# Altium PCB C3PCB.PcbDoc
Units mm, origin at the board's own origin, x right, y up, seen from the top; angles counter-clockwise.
Board outline 50 x 80 mm, 4 copper layers (Top Layer, Int1 (GND), Int2 (PWR), Bottom Layer), stack 1.527 mm thick; 54 components, 42 nets, 181 pads, 145 vias.
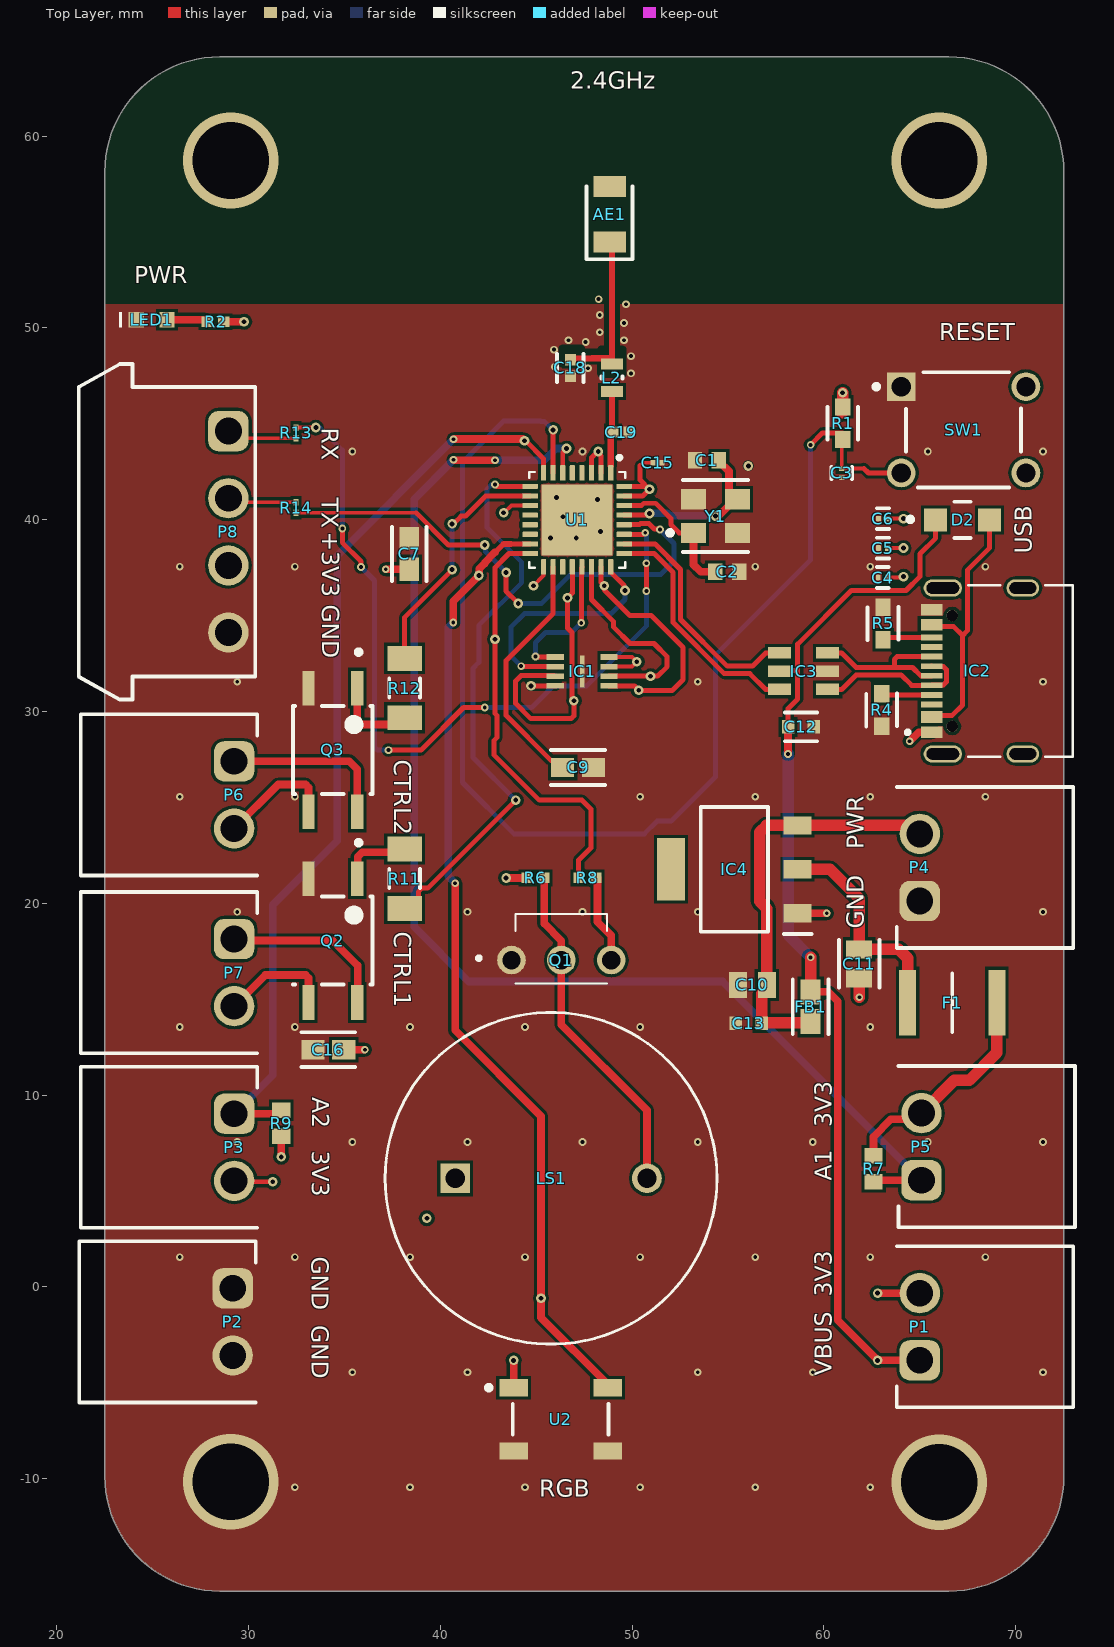
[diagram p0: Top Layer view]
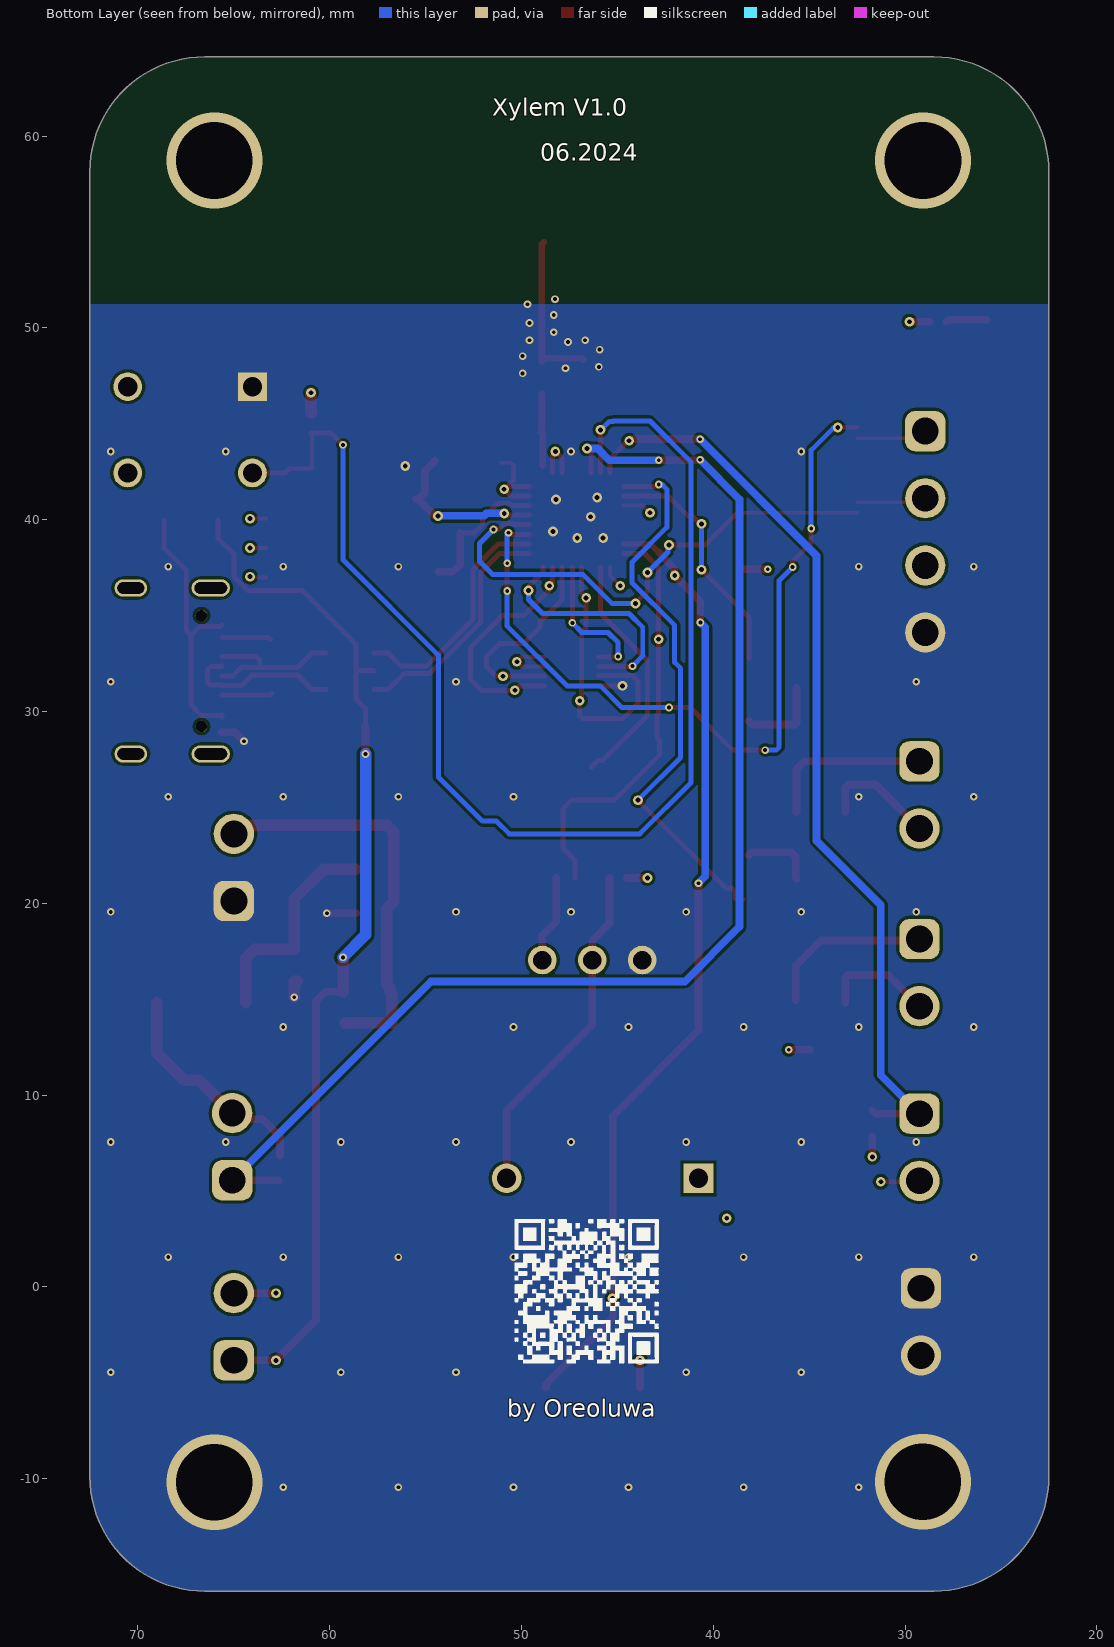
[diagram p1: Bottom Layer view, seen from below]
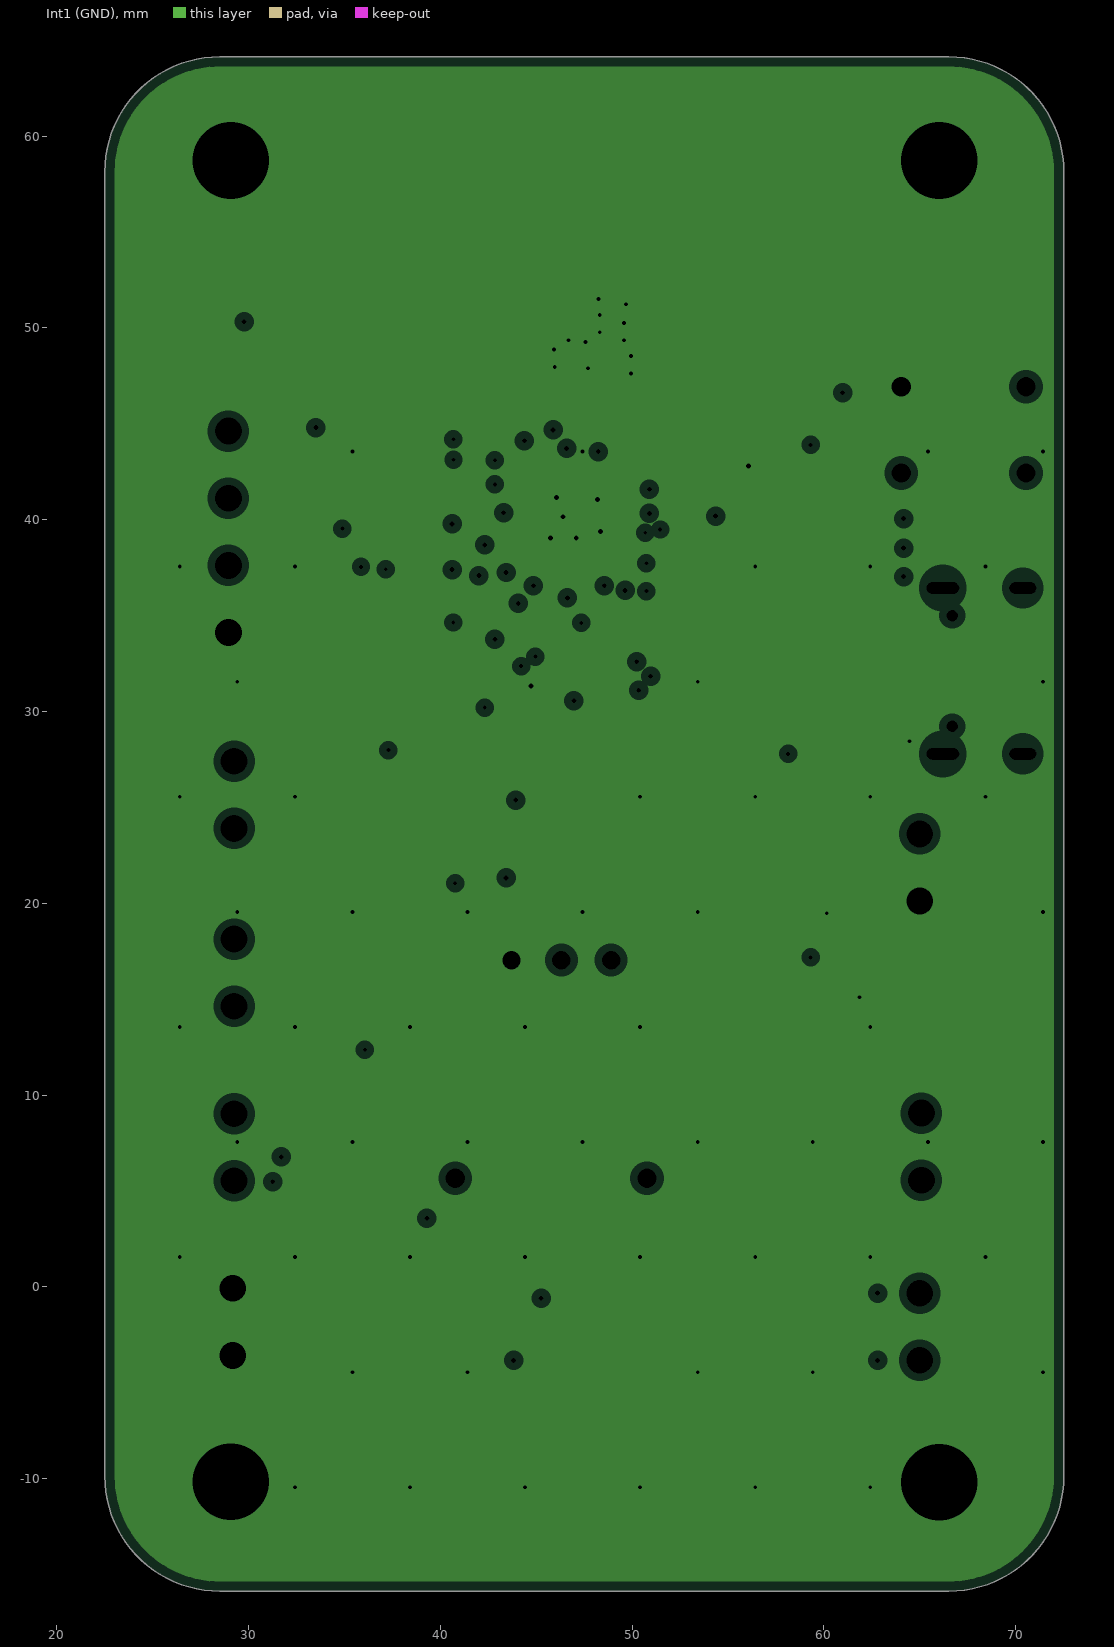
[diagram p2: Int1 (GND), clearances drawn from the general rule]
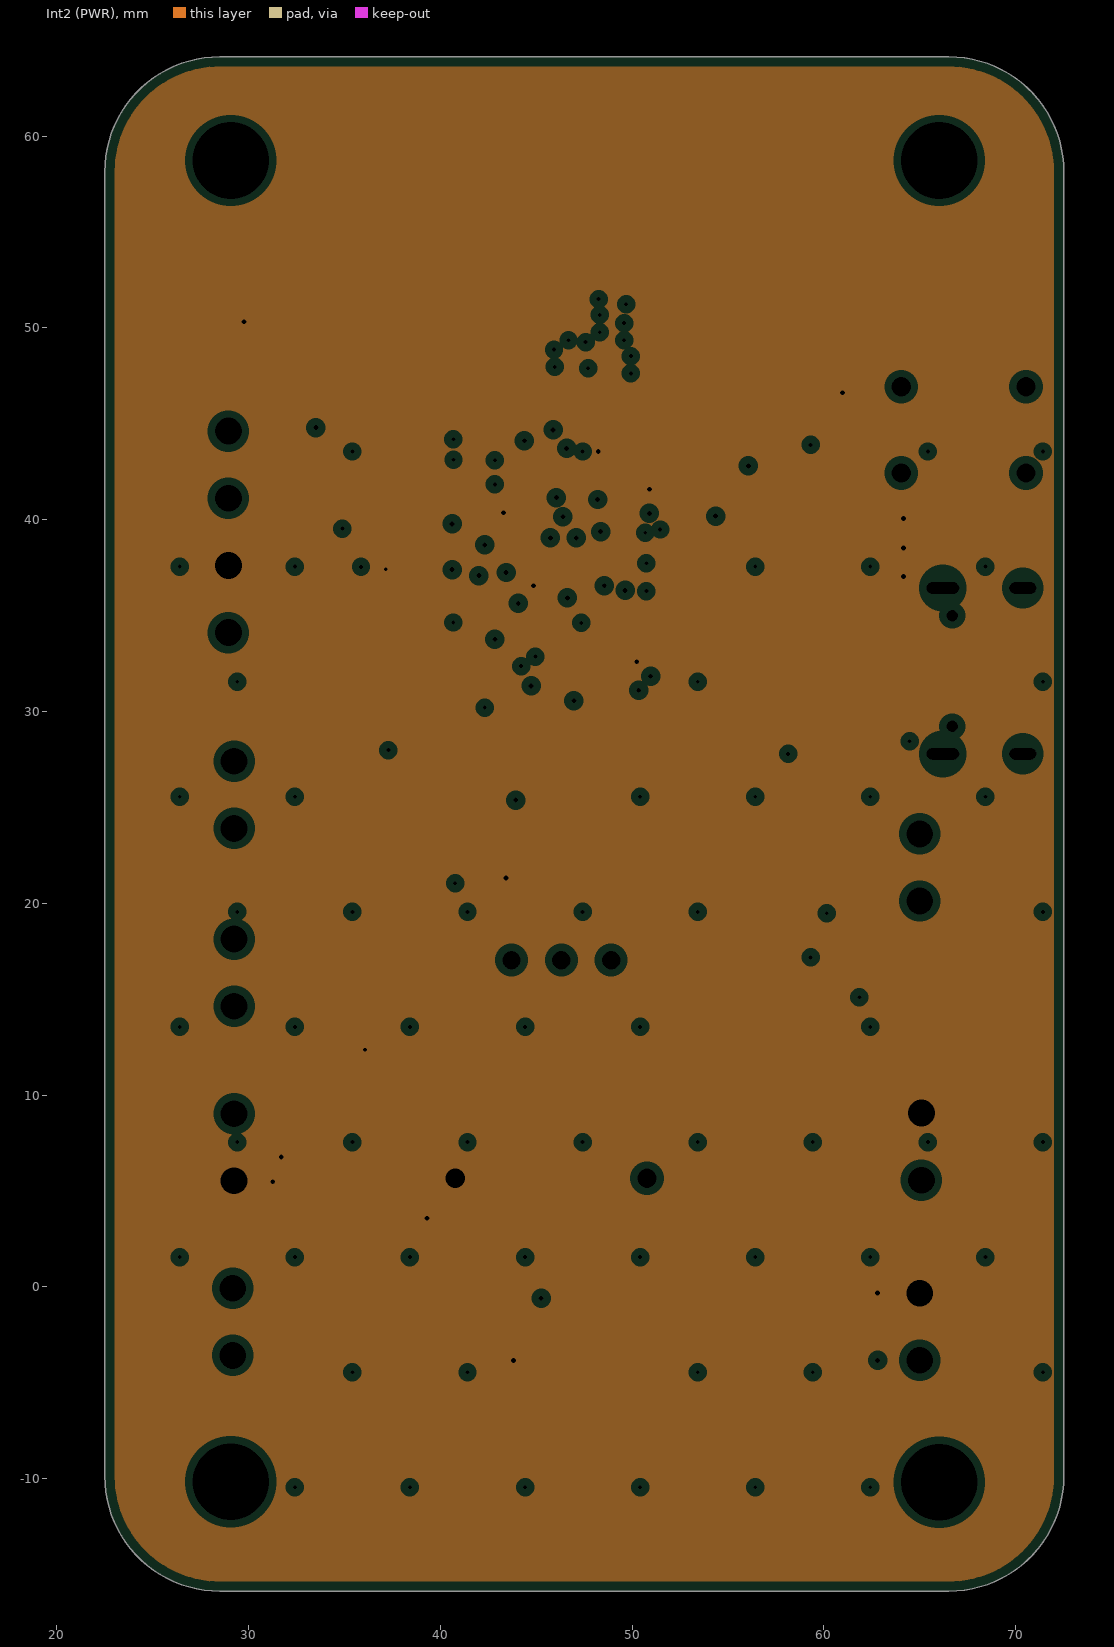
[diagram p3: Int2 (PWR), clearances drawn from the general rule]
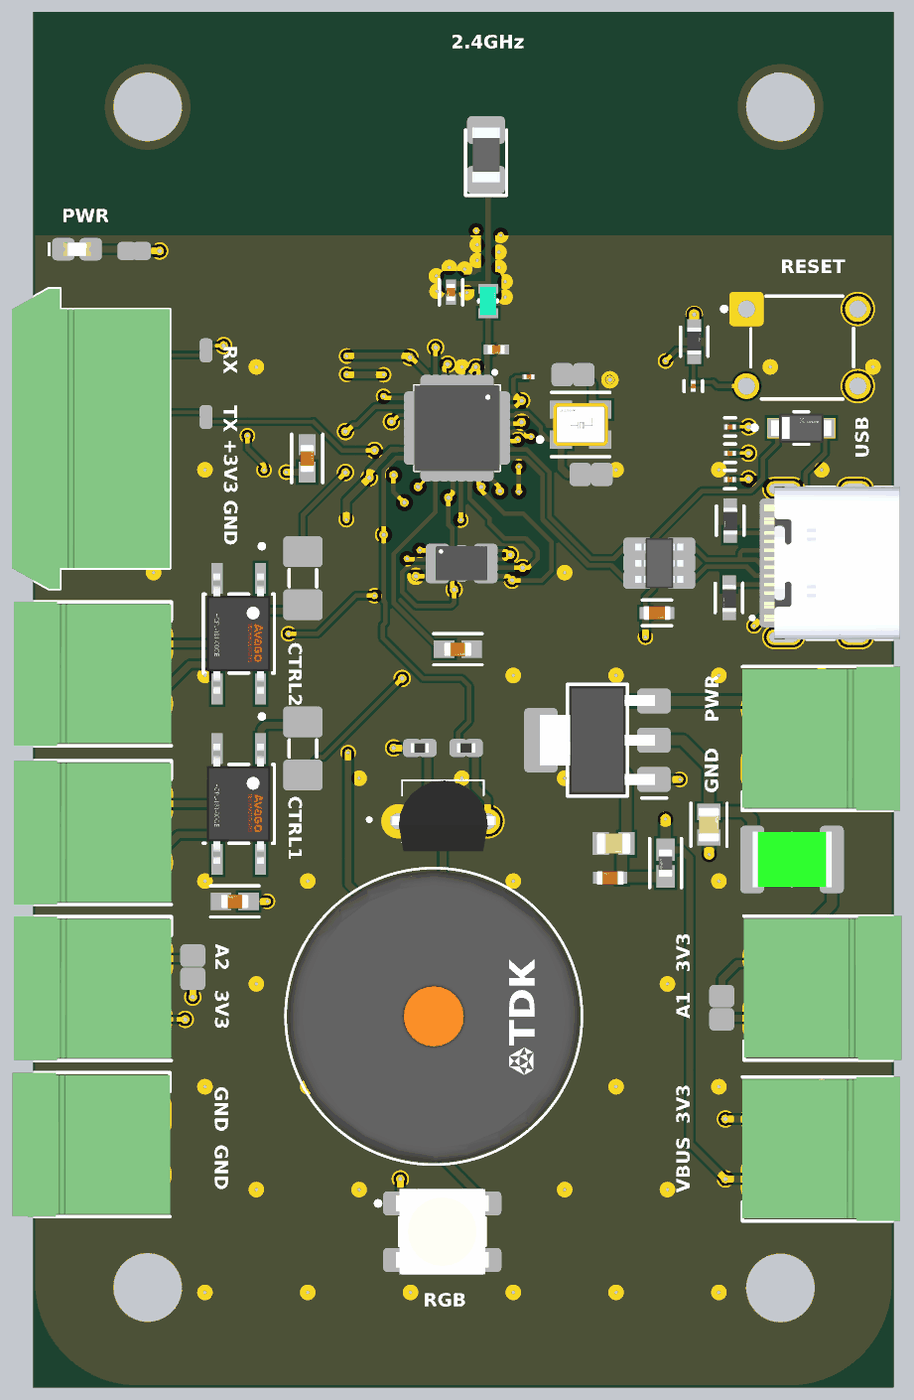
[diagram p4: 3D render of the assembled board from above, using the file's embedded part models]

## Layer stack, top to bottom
Top Solder: solder mask 0.0254, SM-001, Dk 4
Top Layer: signal copper 0.0175
Dielectric 1: prepreg 0.196, PP-017, Dk 4.56
Int1 (GND): plane copper 0.035, net GND
Dielectric 3: core 1.03, Core-039, Dk 4.6
Int2 (PWR): plane copper 0.035, net +3V3
Dielectric 5: prepreg 0.196, PP-017, Dk 4.56
Bottom Layer: signal copper 0.0175
Bottom Solder: solder mask 0.0254, SM-001, Dk 4

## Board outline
22.504,-9.865 22.504,58.135 cw(c28.504,58.135) 28.504,64.135 66.504,64.135 cw(c66.504,58.135) 72.504,58.135 72.504,-9.865 cw(c66.504,-9.865) 66.504,-15.865 28.504,-15.865 cw(c28.504,-9.865)

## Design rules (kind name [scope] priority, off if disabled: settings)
Clearance [All] p1: gap=0.15 ignorepadtopadclearanceinfootprint=TRUE except(0.01: Arc-SMDPad Track-SMDPad SMDPad-SMDPad; 0.1: Arc-Arc Arc-Track Track-Track)
DiffPairsRouting [InDifferentialPair('USBMCU_D')] p1: maxlimit=0.127 minlimit=0.127 mostfreqgap=0.127 toplayer_minwidth=0.26 toplayer_maxwidth=0.26 toplayer_prefwidth=0.26 bottomlayer_minwidth=0.26 bottomlayer_maxwidth=0.26 bottomlayer_prefwidth=0.26 impedanceprofiledriven=TRUE impedanceprofileid={74920327-C2D2-4B69-8C3B-EE058ED59872} impedanceprofilevalue=90.000000 maxuncoupledlength=12.7
DiffPairsRouting DiffPairsRouting_1 [InDifferentialPair('USBIN_D')] p2: maxlimit=0.127 minlimit=0.127 mostfreqgap=0.127 toplayer_minwidth=0.26 toplayer_maxwidth=0.26 toplayer_prefwidth=0.26 bottomlayer_minwidth=0.26 bottomlayer_maxwidth=0.26 bottomlayer_prefwidth=0.26 impedanceprofiledriven=TRUE impedanceprofileid={74920327-C2D2-4B69-8C3B-EE058ED59872} impedanceprofilevalue=90.000000 maxuncoupledlength=12.7
HoleSize [All] p1: absolutevalues=TRUE maxlimit=7.62 minlimit=0.2 maxpercent=80.000 minpercent=20.000
MinimumAnnularRing [All] p1: minimumring=0
MinimumSolderMaskSliver [All] p1: minsoldermaskwidth=0
PasteMaskExpansion [All] p1: expansion=0.254
PlaneClearance [All] p1: clearance=0.381
PlaneConnect [All] p1: pad.planeconnectstyle=Relief pad.reliefexpansion=0.508 pad.reliefentries=4 pad.reliefconductorwidth=0.254 pad.reliefairgap=0.254 via.planeconnectstyle=Direct via.reliefexpansion=0.508 via.reliefentries=4 via.reliefconductorwidth=0.254 via.reliefairgap=0.254
PolygonConnect [All] p1: connectstyle=Direct reliefconductorwidth=0.254 reliefentries=4 polygonreliefangle="90 Angle" airgapwidth=0.254
RoutingVias [All] p1: holewidth=0.3 width=0.508 viastyle="Through Hole" minholewidth=0.19 minwidth=0.3 maxholewidth=15 maxwidth=15
SMDNeckDown [All] p1: percent=150.000
SilkToSilkClearance [All] p1: silktosilkclearance=0.1
SilkToSolderMaskClearance SilkscreenOverComponentPads [IsPad] p1: minsilkscreentomaskgap=0.1 clearancetoexposedcopper=TRUE
SolderMaskExpansion [All] p1: expansion=0.254 istentingtop=FALSE
UnRoutedNet [All] p1: checkbadconnections=TRUE
Width [InNet('ANT_RF')] p1: maxlimit=0.331 minlimit=0.331 preferedwidth=0.331 impedanceprofiledriven=TRUE impedanceprofileid={D2943A05-8640-44C0-B199-8AFC77BF5E13} impedanceprofilevalue=50.000000 minimp=50.000000 maximp=50.000000 favimp=50.000000
21 further rules are at their usual default settings.

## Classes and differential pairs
differential pair class DIF_USB: USBIN_D USBMCU_D
differential pair USBMCU_D: +USBMCU_D_P -USBMCU_D_N
differential pair USBIN_D: +USBIN_D_P -USBIN_D_N

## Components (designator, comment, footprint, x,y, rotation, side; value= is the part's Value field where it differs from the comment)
AE1 "W3008" ANTC3216X115N 48.825,55.925 r90 top
C1 "10pF" CAPC1608X90X35LL10T15 53.898,43.099 r0 top
C2 "10pF" CAPC1608X90X35LL10T15 54.957,37.282 r180 top
C3 "100nF" FP-GRM033-0_03-MFG 60.925,42.435 r270 top
C4 "100nF" FP-GRM033-0_03-MFG 63.064,36.986 r180 top
C5 "100nF" FP-GRM033-0_03-MFG 63.075,38.52 r180 top
C6 "100nF" FP-GRM033-0_03-MFG 63.075,40.054 r180 top
C7 "10u" FP-GRM188-0_1-e0_2_0_55-IPC_A 38.379,38.218 r90 top
C9 "10u" FP-GRM188-0_1-e0_2_0_55-IPC_A 47.177,27.082 r0 top
C10 "22uf/0805" FP-C0805C226M9PACTU-MFG 56.272,15.746 r180 top
C11 "22uf/0805" FP-C0805C226M9PACTU-MFG 61.836,16.846 r270 top
C12 "2u2/0603/15%" FP-GRM188-0_1-e0_2_0_5-MFG 58.801,29.197 r0 top
C13 "2u2/0603/15%" FP-GRM188-0_1-e0_2_0_5-MFG 56.075,13.741 r180 top
C15 "100nF" FP-GRM033-0_03-MFG 51.322,42.97 r0 top
C16 "10u" FP-GRM188-0_1-e0_2_0_55-IPC_A 34.158,12.368 r180 top
C18 "3.3pf/0402" FP-GJM155-0_05-IPC_B 46.775,47.909 r270 top
C19 "3.3pf/0402" FP-GJM155-0_05-IPC_B 49.42,44.57 r0 top
D2 "60A/2A" FP-SOD123W-MFG 67.225,39.988 r0 top
F1 "16V Resetable Fuse" FUSC4632X160N 66.686,14.817 r0 top
FB1 "120R" FP-BLM18-0_15-t0_8-IPC_A 59.301,14.605 r270 top
IC1 "W25Q16JVUXIQ" SON50P300X200X60-9N 47.394,32.089 r0 top
IC2 "TYPE-C-31-M-12" HRO_TYPE-C-31-M-12 70.366,32.114 r90 top
IC3 "USBLC6-2SC6" SOT95P280X145-6N 58.939,32.101 r180 top
IC4 "AMS1117-3.3" SOT229P700X180-4N 55.325,21.772 r180 top
L2 "2.2nH" FP-LQW18AN_80-MFG 48.944,47.403 r90 top
LED1 "GREEN" WL-SMCW_0603_150060xx75000 24.947,50.423 r0 top
LS1 "PS1720P02" FP-PS1720P02-MFG 45.771,5.663 r0 top
P1 "691322110002" 691322110002 68.395,-2.076 r90 top
P2 "691322110002" 691322110002 25.773,-1.822 r270 top
P3 "691322110002" 691322110002 25.85,7.282 r270 top
P4 "691322110002" 691322110002 68.395,21.871 r90 top
P5 "691322110002" 691322110002 68.479,7.311 r90 top
P6 "691322110002" 691322110002 25.85,25.653 r270 top
P7 "691322110002" 691322110002 25.85,16.387 r270 top
P8 "691305140004" 691305140004 25.747,39.368 r270 top
Q1 "KSC1815YTA" BC33740TA 45.408,17.627 r0 top
Q2 "HCPL-181-00CE" FP-SO-4-MFG 34.392,18.059 r270 top
Q3 "HCPL-181-00CE" FP-SO-4-MFG 34.392,27.994 r270 top
R1 "5k1/0603" FP-RT0603-MFG 60.974,45.027 r90 top value=5.1KΩ
R2 "220R/50V/5%" RESC1005X40X25NL05T10 28.281,50.32 r180 top
R4 "5k1/0603" FP-RT0603-MFG 63.011,30.082 r270 top value=5.1KΩ
R5 "5k1/0603" FP-RT0603-MFG 63.079,34.592 r270 top value=5.1KΩ
R6 "1k" RESC1005X40X25NL05T05 44.958,21.322 r180 top
R7 "165R/75V/1%" RESC1608X55X30NL15T15 62.586,6.163 r90 top
R8 "1k/1%/0402" RESC1005X40X25NL05T05 47.663,21.322 r180 top
R9 "165R/75V/1%" RESC1608X55X30NL15T15 31.704,8.532 r270 top
R11 "220R/1216" RESC3216X60X45ML10T20 38.135,21.289 r90 top
R12 "220R/1216" RESC3216X60X45ML10T20 38.135,31.224 r270 top
R13 "470R/25V/1%" RESC0603X26X15LL03T05 32.48,44.524 r270 top
R14 "470R/25V/1%" RESC0603X26X15LL03T05 32.48,40.635 r90 top
SW1 "B3F-1000" OMRON-B3F-1000-4_V 67.277,44.685 r0 top
U1 "ESP32C3" QFN32_5X5MM 47.13,39.988 r270 top
U2 "1655" ADA-RGB-1655_V 46.271,-6.902 r0 top
Y1 "40.000MHZ" FP-ABM8-MFG 54.346,40.19 r0 top

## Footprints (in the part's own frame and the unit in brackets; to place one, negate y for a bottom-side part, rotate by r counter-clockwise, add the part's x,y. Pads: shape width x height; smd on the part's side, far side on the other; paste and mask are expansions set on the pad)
691305140004 [mm] "Horizontal PCB Header with Plastic Latch, pitch 3.5mm, 04p"
  rrect50% 2.1x2.1 hole 1.4: 1(-5.25,3.2)
  round 2.1 hole 1.4: 2(-1.75,3.2) 3(1.75,3.2) 4(5.25,3.2)
  silkscreen extent -8.75,-4.6 8.75,4.6, body extent -8.75,-4.6 8.75,4.6, height 7.25
691322110002 [mm] "Horizontal PCB Header, pitch 3.5mm, 02p"
  rrect50% 2.1x2.1 hole 1.4: 1(-1.75,3.4)
  round 2.1 hole 1.4: 2(1.75,3.4)
  silkscreen extent -4.2,-4.6 4.2,4.6, body extent -4.2,-4.6 4.2,4.6, height 7.3
ADA-RGB-1655_V [mm] "SMD, 4-Leads, Body 5x5mm"
  rect 1.5x0.9 smd: 1(-2.45,1.65) 2(-2.45,-1.65) 3(2.45,-1.65) 4(2.45,1.65)
  silkscreen extent -3.87,-0.8 2.5,1.77, body extent -2.7,-2.5 2.7,2.5, height 1.68
ANTC3216X115N [mm]
  rect 1.1x1.7 smd: 1(-1.45,0) 2(1.45,0)
  silkscreen extent -2.35,-1.2 1.45,1.2, body extent -1.6,-0.8 1.6,0.8, height 1.15
BC33740TA [mm]
  round 1.493 hole 0.96: 1(-1.7,-0.585) 2(0.9,-0.585) 3(3.5,-0.585)
  silkscreen extent -3.5,-1.81 3.28,1.81, body extent -2.16,-2.34 4,1.79, height 8.67
CAPC1608X90X35LL10T15 [mm] "Chip Capacitor, 2-Leads, Body 1.60x0.80mm, IPC High Density"
  rect 0.75x0.85 smd: 1(-0.625,0) 2(0.625,0)
  body extent -0.85,-0.45 0.85,0.45, height 0.9
FP-ABM8-MFG [mm]
  rect 1.3x1.05 smd paste+0 mask+0: 1(-1.15,-0.875) 2(1.15,-0.875) 3(1.15,0.875) 4(-1.15,0.875)
  silkscreen extent -2.5,-1.88 1.7,1.88, body extent -1.9,-1.5 1.9,1.5, height 0.25
FP-BLM18-0_15-t0_8-IPC_A [mm]
  rect 1.306x1.058 smd paste+0 mask+0: 1(-0.776,0) 2(0.776,0)
  silkscreen extent -1.43,-0.93 1.43,0.93, body extent -1.93,-1.03 1.93,1.03, height 0.25
FP-C0805C226M9PACTU-MFG [mm]
  rect 0.95x1.35 smd paste+0 mask+0: 1(-0.75,0) 2(0.75,0)
  body extent -1.4,-0.85 1.4,0.85, height 0.25
FP-GJM155-0_05-IPC_B [mm]
  rect 0.615x0.572 smd paste+0 mask+0: 1(-0.429,0) 2(0.429,0)
  silkscreen extent -0.74,-0.69 0.74,0.69, body extent -0.89,-0.44 0.89,0.44, height 0.25
FP-GRM033-0_03-MFG [mm]
  rect 0.25x0.3 smd paste+0 mask+0: 1(-0.238,0) 2(0.238,0)
  silkscreen extent -0.32,-0.54 0.32,0.54, body extent -0.46,-0.27 0.46,0.27, height 0.25
FP-GRM188-0_1-e0_2_0_5-MFG [mm]
  rect 0.65x0.7 smd paste+0 mask+0: 1(-0.675,0) 2(0.675,0)
  silkscreen extent -0.85,-0.75 0.85,0.75, body extent -1.1,-0.55 1.1,0.55, height 0.25
FP-GRM188-0_1-e0_2_0_55-IPC_A [mm]
  rect 1.208x1.012 smd paste+0 mask+0: 1(-0.802,0) 2(0.802,0)
  silkscreen extent -1.41,-0.91 1.41,0.91, body extent -1.91,-1.01 1.91,1.01, height 0.25
FP-LQW18AN_80-MFG [mm]
  rect 0.57x1.15 smd paste+0 mask+0: 1(-0.715,0) 2(0.715,0)
  silkscreen extent -0.06,-0.55 0.06,0.55, body extent -1.1,-0.67 1.1,0.67, height 0.25
FP-PS1720P02-MFG [mm]
  rect 1.55x1.55 hole 1 paste-2539.97 mask+0: 1(-5,0)
  round 1.55 hole 1 paste-2539.97 mask+0: 2(5,0)
  silkscreen extent -8.65,-8.65 8.65,8.65, body extent -8.75,-8.75 8.75,8.75, height 0.25
FP-RT0603-MFG [mm]
  rect 0.9x0.8 smd paste+0 mask+0: 1(-0.85,0) 2(0.85,0)
  silkscreen extent -0.85,-0.81 0.86,0.8, body extent -1.4,-0.55 1.4,0.55, height 0.25
FP-SO-4-MFG [mm]
  rect 1.8x0.64 smd paste+0 mask+0: 1(-3.23,1.27) 2(-3.23,-1.27) 3(3.23,-1.27) 4(3.23,1.27)
  silkscreen extent -5.23,-2.07 2.3,2.07, body extent -4.23,-2.17 4.23,2.17, height 0.25
FP-SOD123W-MFG [mm]
  rect 1.2x1.2 smd paste-1000 mask+0: 1(-1.4,0) 2(1.4,0)
  silkscreen extent -2.85,-0.95 0.43,0.95, body extent -2.2,-1.05 2.2,1.05, height 0.25
FUSC4632X160N [mm]
  rect 0.89x3.43 smd: 1(-2.325,0) 2(2.325,0)
  silkscreen extent 0,-1.52 0,1.52, body extent -2.3,-1.62 2.3,1.62, height 1.6
HRO_TYPE-C-31-M-12 [mm]
  rect 0.6x1.14 smd mask+0.05: A1_B12(-3.2,4.75) A4_B9(-2.4,4.75) B1_A12(3.2,4.75) B4_A9(2.4,4.75)
  rect 0.3x1.14 smd mask+0.05: A5(-1.25,4.75) A6(-0.25,4.75) A7(0.25,4.75) A8(1.25,4.75) B5(1.75,4.75) B6(0.75,4.75) B7(-0.75,4.75) B8(-1.75,4.75)
  oval 0.9x2 hole 0.6 slot 1.7 at 90 deg: S1(-4.325,4.17) S2(4.325,4.17)
  oval 0.9x1.7 hole 0.6 slot 1.4 at 90 deg: S3(-4.325,0) S4(4.325,0)
  round 0.6 hole 0.6 unplated: ""(-2.89,3.68) ""(2.89,3.68)
  silkscreen extent -4.47,-2.6 4.47,6.1, body extent -4.47,-2.6 4.47,5.31, height 3.31
OMRON-B3F-1000-4_V [mm] "TH, 4-Leads, Body 6x6mm"
  rect 1.5x1.5 hole 1 paste-2539.97: 1(-3.25,2.25)
  round 1.5 hole 1 paste-2539.97: 2(3.25,2.25) 4(3.25,-2.25)
  round 1.5 hole 1 paste-2539.97 mask+0.102: 3(-3.25,-2.25)
  silkscreen extent -4.67,-3 3,3, body extent -3,-3 3,3, height 4.5
QFN32_5X5MM [mm]
  rrect25% 0.81x0.27 smd: 1(-2.45,1.75) 2(-2.45,1.25) 3(-2.45,0.75) 4(-2.45,0.25) 5(-2.45,-0.25) 6(-2.45,-0.75) 7(-2.45,-1.25) 8(-2.45,-1.75) 17(2.45,-1.75) 18(2.45,-1.25) 19(2.45,-0.75) 20(2.45,-0.25) 21(2.45,0.25) 22(2.45,0.75) 23(2.45,1.25) 24(2.45,1.75)
  rrect25% 0.27x0.81 smd: 9(-1.75,-2.45) 10(-1.25,-2.45) 11(-0.75,-2.45) 12(-0.25,-2.45) 13(0.25,-2.45) 14(0.75,-2.45) 15(1.25,-2.45) 16(1.75,-2.45) 25(1.75,2.45) 26(1.25,2.45) 27(0.75,2.45) 28(0.25,2.45) 29(-0.25,2.45) 30(-0.75,2.45) 31(-1.25,2.45) 32(-1.75,2.45)
  rect 3.7x3.7 smd paste-1.4: 33(0,0)
  silkscreen extent -3.35,-2.5 2.5,2.5, body extent -2.5,-2.5 2.5,2.5, height 0.9
RESC0603X26X15LL03T05 [mm] "Chip Resistor, 2-Leads, Body 0.60x0.30mm, IPC High Density"
  rect 0.35x0.25 smd: 1(-0.275,0) 2(0.275,0)
  body extent -0.32,-0.16 0.31,0.17, height 0.26
RESC1005X40X25NL05T05 [mm] "Chip Resistor, 2-Leads, Body 1.05x0.55mm, IPC Medium Density"
  rect 0.55x0.55 smd: 1(-0.45,0) 2(0.45,0)
  body extent -0.53,-0.28 0.53,0.28, height 0.4
RESC1005X40X25NL05T10 [mm] "Chip Resistor, 2-Leads, Body 1.00x0.50mm, IPC Medium Density"
  rect 0.6x0.55 smd: 1(-0.425,0) 2(0.425,0)
  body extent -0.53,-0.27 0.53,0.28, height 0.4
RESC1608X55X30NL15T15 [mm] "Chip Resistor, 2-Leads, Body 1.60x0.80mm, IPC Medium Density"
  rect 0.8x0.95 smd: 1(-0.675,0) 2(0.675,0)
  body extent -0.87,-0.48 0.87,0.48, height 0.55
RESC3216X60X45ML10T20 [mm] "Chip Resistor, 2-Leads, Body 3.20x1.60mm, IPC Low Density"
  rect 1.3x1.8 smd: 1(-1.55,0) 2(1.55,0)
  silkscreen extent -0.5,-0.8 0.5,0.8, body extent -1.65,-0.85 1.65,0.85, height 0.6
SON50P300X200X60-9N [mm]
  rect 0.9x0.3 smd: 1(-1.4,0.75) 2(-1.4,0.25) 3(-1.4,-0.25) 4(-1.4,-0.75) 5(1.4,-0.75) 6(1.4,-0.25) 7(1.4,0.25) 8(1.4,0.75)
  rect 0.25x1.65 smd: 9(0,0)
  body extent -1.5,-1 1.5,1, height 0.6
SOT95P280X145-6N [mm]
  rect 1.2x0.6 smd: 1(-1.25,0.95) 2(-1.25,0) 3(-1.25,-0.95) 4(1.25,-0.95) 5(1.25,0) 6(1.25,0.95)
  body extent -1.4,-1.46 1.4,1.46, height 1.45
SOT229P700X180-4N [mm]
  rect 1.45x0.95 smd: 1(-3.3,2.29) 2(-3.3,0) 3(-3.3,-2.29)
  rect 1.45x3.25 smd: 4(3.3,0)
  silkscreen extent -4.04,-3.25 1.75,3.37, body extent -3.35,-3.15 3.35,3.15, height 1.8
WL-SMCW_0603_150060xx75000 [mm] "SMD Mono-color Chip LED, body 1.6x0.8mm"
  rect 0.8x0.8 smd: 1(-0.8,0) 2(0.8,0)
  silkscreen extent -1.71,-0.4 -1.56,0.4, body extent -0.8,-0.4 0.8,0.4, height 0.7

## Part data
AE1: "Antenna", Manufacturer_Name=PULS
C1 C2: library part CMP-2006-02592-1, Manufacturer=Murata, Part Number=GRM1885C1H100JA01D
C3 C4 C5 C6 C15: library part CMP-06035-000062-2, "Chip Multilayer Ceramic Capacitors for General Purpose, 0201, 0.10uF, X5R, 15%, 10%, 6.3V", Case Code (Imperial)=0201, Case Code (Metric)=0603, Dielectric=X5R, Max Operating Temperature=85°C, Min Operating Temperature=-55°C, Package Quantity=1, Tolerance=10%, Voltage=6.3V
C7 C9 C16: library part CMP-2006-02792-2, "Chip Multilayer Ceramic Capacitors for General Purpose, 0603, 10uF, X5R, 15%, 20%, 6.3V", Capacitance=10uF, Case Code (Imperial)=0603, Case Code (Metric)=1608, Dielectric=X5R, Max Operating Temperature=85°C, Min Operating Temperature=-55°C, Package Quantity=4000, Tolerance=20%, Voltage=6.3V
C10 C11: library part CMP-2007-01021-2, "CAP CER 22UF 6.3V X5R 0805", Capacitance=22uF, Case Code (Imperial)=0805, Case Code (Metric)=2012, Dielectric=X5R, Dielectric Material=Ceramic, Max Operating Temperature=85°C, Min Operating Temperature=-55°C, Package Quantity=2500, Tolerance=20%, Voltage=6.3V
C12 C13: library part CMP-2006-02836-2, "Chip Multilayer Ceramic Capacitors for General Purpose, 0603, 2.2uF, X7R, 15%, 10%, 10V", Capacitance=2.2uF, Case Code (Imperial)=0603, Case Code (Metric)=1608, Dielectric=X7R, Max Operating Temperature=125°C, Min Operating Temperature=-55°C, Package Quantity=1, Tolerance=10%, Voltage=10V
C18 C19: library part CMP-2008-03847-2, "Multi-Layer Ceramic Capacitor 3.3pF C0G  ±0.25pF 0402 Paper T/R", Capacitance=3.3pF, Case Code (Imperial)=0402, Case Code (Metric)=1005, Dielectric=C0G, Max Operating Temperature=125°C, Min Operating Temperature=-55°C, Package Quantity=1, Voltage=50V
D2: library part CMP-14398-000040-1, "DIODE SCHOTTKY 60V 2A CFP3"
F1: library part MF-MSMF250_16X, "Fuse", Manufacturer_Name=Bourns, Manufacturer_Part_Number=MF-MSMF250/16X
FB1: library part CMP-0686-00557-7, "Chip Ferrite Bead, 0603, 120Ω @ 100MHz, 0.05Ω, 25%, 2A", Case Code (Imperial)=0603, Case Code (Metric)=1608, Current Rating=2A, DC Resistance (DCR)=50mR, Frequency=100MHz, Max Operating Temperature=125°C, Min Operating Temperature=-55°C, Package Quantity=1, Tolerance=25%
IC1: library part CMP-031-00015-1, "NOR Flash Serial (SPI, Dual SPI, Quad SPI) 3V/3.3V 16M-bit 2M x 8 6ns 8-Pin USON EP T/R", Case/Package="UFDFN-8 Winbond"
IC2: library part CMP-002-00071-1, "USB Connectors 24 Receptacle 1 8.94*7.3mm RoHS", Case/Package=Package
IC3: "Integrated Circuit", Manufacturer_Name=STMicroelectronics, Mouser Part Number=511-USBLC6-2SC6
IC4: "Integrated Circuit", Manufacturer_Name=Advanced
L2: library part CMP-06042-009804-1, "Wire Wound RF Inductor 2.2nH ±0.2nH 3200mA 0.018Ω 0603 (1608)", Case/Package=0603, Current Rating=3.2A, DC Resistance (DCR)=18mR, Max Operating Temperature=125°C, Min Operating Temperature=-55°C, Package Quantity=4000, Resistor Type=Wirewound, Self Resonant Frequency=15GHz, Test Frequency=100MHz
LED1: library part CMP-1426-00006-6, Case Code (Imperial)=0603, Case Code (Metric)=1608, Color=Green, Forward Current=100mA, Forward Voltage=2V, Max Junction Temperature (Tj)=95°C, Max Operating Temperature=85°C, Max Reverse Voltage (DC)=5V, Min Operating Temperature=-40°C, Power Dissipation=72mW, Test Current=20mA
LS1: library part CMP-08413-000001-1, "AUDIO PIEZO TRANSDUCER 30V TH", Frequency=2kHz, Manufacturer="TDK Corporation", Package=0, Temperature="-10°C to +70°C", Temperature Range High=+70°C, Temperature Range Low=-10°C
P1 P2 P3 P4 P5 P6 P7: library part CMP-1502-01791-3, Color=Green, Current=10A, Max Operating Temperature=105°C, Min Operating Temperature=-40°C, Voltage=300V
P8: library part CMP-1502-01777-2
Q1: library part CMP-030-000000-1, "Transistor", Manufacturer_Name=onsemi, Mouser Part Number=512-KSC1815YTA
Q2 Q3: library part CMP-18400-000021-1, "OPTOISO 3.75KV TRANS 4MINIFLAT", Ambient Temperature Range High=+100°C, Ambient Temperature Range Low=-55°C, Collector Emitter Voltage=80V, Emiiter Collector Voltage=6V, Forward Current=20mA, Forward Voltage=1.2V, Isolation Voltage=3750Vrms, Manufacturer=Broadcom, Max Current Transfer Ratio=400%, Min Current Transfer Ratio=200%, Package=SO-4, Power Dissipation=170mW, Temperature="-55°C to +100°C"
R1 R4 R5: library part CMP-2000-04778-2, "RES SMD 5.1K OHM 1% 1/10W 0603", Manufacturer=Yageo, Manufacturer Part Number=RT0603FRE075K1L, Package=RT0603, Power Rating=0.1W, Resistance=5.1KΩ, Temperature="-55°C to +155°C", Temperature Coefficient="50 ppm/°C", Temperature Range High=+155°C, Temperature Range Low=-55°C, Tolerance=0.01, Voltage Rating=75V
R2: library part CMP-2002-07959-1, Manufacturer="Yageo / Phycomp", Part Number=RC0402JR-07220RL
R6 R8: library part CMP-1011-00510-4, "Chip Resistor, 1 KOhm, +/- 1%, 100 mW, -55 to 155 degC, 0402 (1005 Metric), RoHS, Tape and Reel", Case Code (Imperial)=0402, Case Code (Metric)=1005, Manufacturer="Basic Passives", Max Operating Temperature="155 degC", Min Operating Temperature="-55 degC", Package Quantity=10000, PartNumber=ERJ-2RKF1001X, Power Rating="100 mW", Resistance="1 KOhm", Tolerance=1%, Voltage Rating="50 V"
R7 R9: library part CMP-2000-00277-1, Manufacturer=Panasonic, Part Number=ERJ-3EKF1650V
R11 R12: library part CMP-2003-01956-1, Manufacturer="Vishay Dale", Part Number=CRCW1206220RFKEA
R13 R14: library part CMP-1010-00379-2, Manufacturer=Panasonic, Part Number=ERJ1GNF4700C
SW1: library part CMP-1677-00002-1, "Tactile Switch, SPST-NO, 0.05 A, 5 to 24 V, -25 to 70 degC, 4-Pin THD, RoHS, Bulk", Capacitance="-45 f", Current Rating="1.5 A", Max Operating Temperature="70 degC", Min Operating Temperature="-40 degC", Package Quantity=1080, Voltage Rating="150 V"
U1: library part CMP-031-00006-1, "WiFi Modules (802.11) (Engineering Samples Only) SMD IC ESP32-C3, RISC-V single-core MCU, 2.4G Wi-Fi & BLE 5.0 combo, QFN 32-pin, 5*5 mm, 40 ~ 105C", Case/Package="VFQFN-32 Espressif Systems"
U2: library part CMP-2000-05026-1, "Intelligent Control LED Integrated Light Source, 3.5 to 5.3 V, -25 to 80 degC, 4-Pin SMD, RoHS, Tape and Reel", Color=Red,Green,Blue(RGB), Manufacturer=Adafruit-Industries-LLC, Package Description="4-Pin Surface Mount Device, Body 5 x 5 mm"
Y1: library part CMP-27762-008947-1, "Crystal 40MHz ±10ppm 10pF SMD-4 3.2mm x 2.5mm", Case/Package=SMD/SMT, ESR (Equivalent Series Resistance)=35R, Frequency=40MHz, Frequency Stability=10ppm, Load Capacitance=10pF, Max Operating Temperature=60°C, Min Operating Temperature=-10°C, Operating Frequency="40 MHz", Package Quantity=1000, Resistor Type=Ceramic

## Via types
v1: diameter 0.4, hole 0.2, Top Layer to Bottom Layer, 95 vias
v2: diameter 0.508, hole 0.254, Top Layer to Bottom Layer, 46 vias
v3: diameter 5, hole 4, Top Layer to Bottom Layer, 4 vias

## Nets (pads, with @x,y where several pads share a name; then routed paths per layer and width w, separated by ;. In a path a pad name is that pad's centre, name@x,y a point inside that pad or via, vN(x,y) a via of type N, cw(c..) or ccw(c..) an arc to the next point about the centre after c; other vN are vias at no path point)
+3V3: C4.1 C5.1 C6.1 C7.1 C15.1 C16.1 F1.2 IC1.7 IC1.8 LS1.1 P1.2 P3.2 P5.2 P8.3 R1.2 R2.1 R6.2 R7.2 R9.2 U1.2 U1.3 U1.11 U1.17 U1.31 U1.32 U2.1 | length 39.8
  Top Layer w0.18: 50.414,42.821 50.563,42.97 C15.1
  Top Layer w0.2: v2(43.299,40.36) 43.326,40.36 43.704,40.738 U1.11 ; v2(44.85,36.555) 45.38,37.085 U1.17 ; IC1.7 49.986,32.339 v2(50.241,32.594) 49.995,32.839 IC1.8 ; C4.1 v2@64.103,36.986 ; C5.1 v2(64.147,38.52) ; C6.1 v2(64.147,40.054)
  Top Layer w0.254: P3.2 29.296,5.486 v2(31.263,5.486) ; U1.3 47.88,43.238 48.193,43.55 v2(48.232,43.55) 48.232,43.482 48.38,43.333 U1.2 ; U1.31 50.553,41.238 v2(50.9,41.585) 50.414,42.071 50.414,42.821 ; U1.32 50.679,41.738 ; R1.2@60.925,45.579 R1.2@60.974,45.529 ; v2@64.103,36.986 v2(64.147,37.03)
  Top Layer w0.4: R2.1 v2(29.769,50.32) ; v2(31.704,6.782) R9.2 ; C16.1 v1(36.064,12.368) ; v1(37.155,37.416) C7.1 ; v2(43.429,21.322) R6.2 ; U2.1 v2(43.821,-3.826) ; R7.2 62.586,7.838 63.483,8.735 64.754,8.735 P5.2 ; v2(62.796,-0.326) P1.2
  Top Layer w0.6: R1.2@60.938,45.563 60.975,45.563 v2(60.975,46.618) ; P5.2 66.793,10.775 67.583,10.775 69.011,12.202 F1.2
  other v2: 39.294,3.581
+SPI_VCC: C9.1 U1.18 | length 12.8
  Top Layer w0.26: U1.18 45.88,35.112 43.429,32.661 43.429,29.789 45.76,27.458 46,27.458 C9.1
ADC1: P5.1 R7.1 U1.6 | length 67.2
  Top Layer w0.26: U1.6 46.38,43.514 v2(46.582,43.716) ; R7.1 R7.1@62.658,5.561
  Top Layer w0.4: v1(40.685,43.121) 40.708,43.099 v1(42.845,43.099) ; R7.1@62.658,5.561 P5.1
  Bottom Layer w0.4: v1(40.685,43.121) 38.635,41.07 38.635,18.771 41.485,15.921 54.719,15.921 P5.1 ; v1(42.845,43.099) 45.417,43.099 46.035,43.716 v2(46.582,43.716)
ADC2: P3.1 R9.1 U1.8 | length 48.3
  Top Layer w0.26: v2(44.384,44.114) 44.447,44.114 45.38,43.181 U1.8
  Top Layer w0.4: P3.1 31.529,9.032 R9.1 ; v1(40.682,44.191) 40.7,44.209 44.289,44.209 v2(44.384,44.114)
  Bottom Layer w0.4: P3.1 31.263,11.045 31.263,19.913 34.618,23.268 34.618,38.127 v1(40.682,44.191) v1@40.7,44.209
ANT_RF: AE1.1 C18.1 L2.2 | length 8.6
  Top Layer w0.331: C18.1 46.844,48.407 47.913,48.407 47.915,48.409 48.764,48.409 48.944,48.23 48.944,54.356 AE1.1
ANTENNA_IN: C19.1 L2.1 U1.1 | length 3.9
  Top Layer w0.331: U1.1@48.88,42.805 48.88,44.553 C19.1@48.944,44.617 ; L2.1@48.944,46.577 C19.1@48.944,44.617 ; C19.1 C19.1@48.944,44.617
BUZZ: R8.2 U1.16 | length 22.1
  Top Layer w0.26: U1.16 43.582,38.238 42.845,37.501 v2(42.845,33.765) 42.845,29.902 42.945,29.802 42.945,28.635 42.791,28.481 42.791,27.743 45.156,25.377 47.388,25.377 47.844,24.921 47.844,22.886 47.213,22.255 R8.2
BUZZ_T1: LS1.2 Q1.2 R6.1 | length 17.9
  Top Layer w0.4: R6.1 45.408,18.949 46.308,18.05 Q1.2 46.308,13.67 50.771,9.207 LS1.2
BUZZNPN_RES: Q1.3 R8.1 | length 4.6
  Top Layer w0.4: R8.1@48.188,21.322 48.188,19.042 48.908,18.322 Q1.3
CC1: IC2.A5 R4.1 | length 2.6
  Top Layer w0.254: R4.1 63.079,30.864 IC2.A5
CC2: IC2.B5 R5.2 | length 2.6
  Top Layer w0.254: R5.2 63.201,33.864 IC2.B5
CHIP_EN: C3.1 R1.1 SW1.3 U1.7 | length 66.6
  Top Layer w0.2: R1.1@60.925,44.475 C3.1 62.081,42.673
  Top Layer w0.26: U1.7 v2(45.88,44.685) ; v1(59.301,43.901) 59.925,44.525 R1.1@60.972,44.525 ; 62.081,42.673 62.318,42.435 SW1.3
  Bottom Layer w0.26: v2(45.88,44.685) 45.855,44.685 45.412,45.128 45.228,45.128 45.208,45.149 43.299,45.149 41.15,43 41.15,26.3 43.829,23.621 50.638,23.621 51.298,24.282 52.025,24.282 54.332,26.588 54.332,32.935 59.301,37.905 v1(59.301,43.901)
Control1: R11.1 U1.9 | length 29.2
  Top Layer w0.26: R11.1@38.454,20.205 38.798,20.205 38.852,20.259 38.852,20.603 39.036,20.787 39.337,20.787 v2(43.928,25.377) ; v1(42.845,41.838) 42.945,41.738 U1.9
  Bottom Layer w0.26: v1(42.845,41.838) 42.673,41.838 42.421,41.585 42.421,39.605 44.236,37.789 44.236,36.72 42.008,34.491 42.008,32.562 41.7,32.254 41.7,27.605 v2(43.928,25.377)
Control2: R12.1 U1.10 | length 12.7
  Top Layer w0.26: R12.1 38.135,34.914 v2(40.616,37.395) ; v2(40.616,39.782) 40.683,39.782 41.085,40.184 41.309,40.184 42.363,41.238 U1.10
  Bottom Layer w0.26: v2(40.616,37.395) v2(40.616,39.782)
CRTL1_IN: P7.1 Q2.4 | length 8.8
  Top Layer w0.4: P7.1 29.327,18.059 34.392,18.059 35.696,16.755 Q2.4@35.696,14.943
CRTL1_IN_RES: Q2.1 R11.2 | length 3.7
  Top Layer w0.4: Q2.1 35.696,21.323 35.696,22.421 35.93,22.655 37.986,22.655 R11.2@38.135,22.506
CRTL1_OUT: P7.2 Q2.3 | length 5.9
  Top Layer w0.4: P7.2 30.872,16.259 32.973,16.259 33.122,16.11 Q2.3
CRTL2_IN: P6.1 Q3.4 | length 8.8
  Top Layer w0.4: P6.1 35.254,27.403 35.662,26.995 Q3.4
CRTL2_IN_RES: Q3.1 R12.2 | length 4.4
  Top Layer w0.4: Q3.1 35.662,29.399 35.742,29.319 37.953,29.319 R12.2@38.135,29.501
CRTL2_OUT: P6.2 Q3.3 | length 6.2
  Top Layer w0.4: P6.2 31.541,26.194 32.97,26.194 33.122,26.042 Q3.3
GND: C1.1 C2.1 C3.2 C4.2 C5.2 C6.2 C7.2 C9.2 C10.2 C11.2 C12.2 C13.2 C15.2 C16.2 C18.2 C19.2 IC1.4 IC1.9 IC2.A1_B12 IC2.B1_A12 IC3.2 IC4.1 LED1.1 P2.1 P2.2 P4.1 P8.4 Q1.1 Q2.2 Q3.2 R4.2 R5.1 SW1.1 U1.33 U2.2 U2.3 Y1.2 Y1.4 | length 5.4
  Top Layer w0.254: v2(44.727,31.339) IC1.4 ; v2@56.046,42.816 v2(56.057,42.805) ; C11.2@61.676,15.936 C11.2
  Top Layer w0.4: IC4.1 v1(60.144,19.482) ; v1(64.466,28.447) 64.933,28.914 IC2.A1_B12
  Top Layer w0.6: C11.2@61.676,15.936 61.831,15.936 61.847,15.921 v1(61.847,15.105)
  other v1: 32.414,-10.446 38.414,-10.446 44.414,-10.446 50.414,-10.446 56.414,-10.446 62.414,-10.446 35.414,-4.446 41.414,-4.446 53.414,-4.446 59.414,-4.446 71.414,-4.446 26.414,1.554 32.414,1.554 38.414,1.554 44.414,1.554 50.414,1.554 56.414,1.554 62.414,1.554 68.414,1.554 29.414,7.554 35.414,7.554 41.414,7.554 47.414,7.554 53.414,7.554 59.414,7.554 65.414,7.554 71.414,7.554 26.414,13.554 32.414,13.554 38.414,13.554 44.414,13.554 50.414,13.554 62.414,13.554 29.414,19.554 35.414,19.554 41.414,19.554 47.414,19.554 53.414,19.554 71.414,19.554 26.414,25.554 32.414,25.554 50.414,25.554 56.414,25.554 62.414,25.554 68.414,25.554 29.414,31.554 53.414,31.554 71.414,31.554 26.414,37.554 32.414,37.554 56.414,37.554 62.414,37.554 68.414,37.554 35.414,43.554 47.414,43.554 65.414,43.554 71.414,43.554 49.936,47.628 47.698,47.892 45.965,47.968 49.936,48.528 45.924,48.867 47.574,49.261 46.679,49.356 49.576,49.352 48.313,49.775 49.576,50.252 48.313,50.675 49.682,51.232 48.253,51.5
  other v2: 45.741,39.049 47.087,39.049 48.354,39.384 46.391,40.152 48.195,41.053 46.052,41.152
  other v3: 66.01,-10.184 29.07,-10.159 29.07,58.726 66.011,58.725
PWR_LED: LED1.2 R2.2 | length 2.2
  Top Layer w0.4: LED1.2 27.753,50.423 R2.2
RBG_LED: U1.15 U2.4 | length 50
  Top Layer w0.25: 43.675,38.738 U1.15
  Top Layer w0.3: 42.845,38.295 43.288,38.738 43.675,38.738
  Top Layer w0.4: v1(40.67,34.64) 40.67,35.748 42.028,37.106 42.028,37.436 42.311,37.718 42.311,37.761 42.845,38.295 ; v1(40.771,21.047) 40.771,13.375 45.247,8.899 v2(45.247,-0.587) 45.247,-1.596 48.721,-5.07 U2.4
  Bottom Layer w0.4: v1(40.67,34.64) 40.415,34.385 40.415,21.404 v1(40.771,21.047)
  other v2: 42.008,37.085
SPI_CLK: IC1.6 U1.22 | length 10.8
  Top Layer w0.26: U1.22 47.88,35.837 49.032,34.686 49.032,34.394 49.884,33.542 51.138,33.542 51.822,32.857 51.822,32.339 51.322,31.839 v2(50.96,31.839) IC1.6
SPI_CS: IC1.1 U1.21 | length 7.5
  Top Layer w0.26: v1(44.958,32.864) 44.971,32.851 45.982,32.851 IC1.1 ; v1(47.346,34.622) 47.346,37.504 U1.21
  Bottom Layer w0.26: v1(44.958,32.864) 44.958,33.593 45.483,34.118 46.842,34.118 v1(47.346,34.622)
SPI_DI: IC1.5 U1.23 | length 12.5
  Top Layer w0.26: U1.23 48.38,36.719 v2(48.544,36.555) 48.544,36.333 49.873,35.004 50.986,35.004 52.646,33.343 52.646,31.659 52.076,31.089 50.367,31.089 v2(50.344,31.111) 50.117,31.339 IC1.5
SPI_DO: IC1.2 U1.24 | length 12.6
  Top Layer w0.26: v1(44.211,32.364) 44.236,32.339 IC1.2 ; U1.24 48.88,37.268 49.583,36.565 49.583,36.36 v2(49.63,36.312)
  Bottom Layer w0.26: v1@44.236,32.339 v1(44.211,32.364) 43.675,32.9 43.675,34.394 44.393,35.112 48.906,35.112 49.63,35.837 v2(49.63,36.312)
SPI_WP: IC1.3 U1.20 | length 14.8
  Top Layer w0.26: IC1.3 45.96,31.873 44.211,31.873 43.928,31.589 43.928,30.414 44.718,29.624 46.808,29.624 46.96,29.776 v2(46.96,30.561) 46.859,30.663 46.859,34.118 46.625,34.352 v2(46.625,35.927) 46.88,36.182 U1.20
UART_RX: R13.1 U1.27 | length 42
  Top Layer w0.2: R13.1 v2@33.506,44.799
  Top Layer w0.26: v1(34.892,39.538) 34.892,38.799 35.862,37.829 v1(35.862,37.538) ; v1(37.294,27.988) 38.988,27.988 41.207,30.207 v1(42.311,30.207) ; U1.27 50.601,39.238 v1(50.679,39.315) ; v1(50.74,36.279) v1(50.74,37.732)
  Bottom Layer w0.26: v2(33.507,44.8) 33.719,44.8 34.892,43.627 v1(34.892,39.538) ; v1(35.862,37.538) 36.567,36.833 36.567,28.14 36.719,27.988 v1(37.294,27.988) ; v1(42.311,30.207) 44.762,30.207 45.894,31.339 47.626,31.339 50.74,34.453 v1(50.74,36.279) ; v1(50.679,39.315) 50.679,39.278 50.74,39.216 v1(50.74,37.732)
UART_RX_PRT: P8.1 R13.2 | length 3.7
  Top Layer w0.2: P8.1 29.317,44.249 R13.2
UART_TX: R14.1 U1.28 | length 27.3
  Top Layer w0.2: R14.1 38.74,40.36
  Top Layer w0.26: 38.74,40.36 40.415,38.685 v2(42.311,38.685) ; v2(43.429,37.247) 43.416,37.234 43.416,36.279 v2(44.058,35.637) ; U1.28 50.375,39.738 50.433,39.796 50.878,39.796 51.159,39.514 51.426,39.514 v1(51.453,39.488)
  Bottom Layer w0.26: v2(42.311,38.685) 42.358,38.638 42.358,38.318 v2(43.429,37.247) ; v2(44.058,35.637) 45.283,35.637 46.797,37.151 51.506,37.151 52.182,37.827 52.182,38.758 v1(51.453,39.488)
UART_TX_PRT: P8.2 R14.2 | length 3.6
  Top Layer w0.2: P8.2 29.156,40.91 R14.2
USB_VBUS_OUT: D2.2 IC2.A4_B9 IC2.B4_A9 | length 14
  Top Layer w0.254: IC2.A4_B9 65.616,29.801 66.686,29.801 67.225,30.34 67.225,33.965 ; IC2.B4_A9 65.703,34.427 66.763,34.427 67.225,33.965 ; D2.2 68.625,38.52 67.473,37.368 67.473,34.213 67.225,33.965
USBIN: C10.1 C13.1 FB1.2 IC4.3 P4.2 | length 21.5
  Top Layer w0.26: FB1.2@59.214,13.741 FB1.2
  Top Layer w0.6: FB1.2@59.214,13.741 59.17,13.785 56.775,13.785 56.75,13.76 C13.1 56.75,15.274 56.847,15.371 56.847,15.571 C10.1 57.022,19.729 56.649,20.102 56.649,23.711 57,24.062 64.147,24.062 64.589,23.621 P4.2
USBIN_D_N: IC2.A7 IC2.B7 IC3.1 | length 8.3
  Top Layer w0.26: IC3.1 60.919,31.151 61.676,31.907 64.027,31.907 64.571,31.364 IC2.B7 65.636,31.384 66.222,31.384 66.375,31.536 66.375,32.191 66.222,32.344 65.636,32.344 IC2.A7
USBIN_D_P: IC2.A6 IC2.B6 IC3.3 | length 8.3
  Top Layer w0.26: IC3.3 60.919,33.051 61.676,32.294 63.666,32.294 ; IC2.A6 65.046,31.864 64.615,32.294 63.666,32.294 ; IC2.B6 63.818,32.864 63.666,32.711 63.666,32.294
USBMCU_D_N: IC3.6 U1.25 | length 12.6
  Top Layer w0.26: U1.25 51.145,38.238 52.136,37.247 52.136,34.64 54.8,31.976 56.134,31.976 56.959,31.151 IC3.6
USBMCU_D_P: IC3.4 U1.26 | length 12.6
  Top Layer w0.26: U1.26 51.193,38.738 52.523,37.407 52.523,34.801 54.96,32.364 56.272,32.364 56.959,33.051 IC3.4
VBUS: C12.1 D2.1 FB1.1 IC3.5 P1.1 | length 54.3
  Top Layer w0.26: IC3.5 57.715,32.126 58.527,32.126 58.625,32.224 ; C12.1 58.126,30.151 58.625,30.65 58.625,32.224 ; D2.1 65.825,39.038 64.995,38.207 64.995,37.03 64.277,36.312 61.425,36.312 58.625,33.513 58.625,32.224
  Top Layer w0.4: v1(58.126,27.789) C12.1 ; FB1.1 60.228,15.381 60.713,14.896 60.713,-1.743 v2(62.796,-3.826) P1.1
  Top Layer w0.6: FB1.1 v1(59.301,17.18)
  Bottom Layer w0.6: v1(58.126,27.789) 58.126,18.355 v1(59.301,17.18)
VOUT_3V3: C11.1 F1.1 IC4.2 | length 11.5
  Top Layer w0.6: IC4.2 60.313,21.772 61.836,20.25 C11.1 63.902,17.596 64.361,17.137 F1.1
XTAL_NM: C1.2 U1.29 Y1.3 | length 8.9
  Top Layer w0.26: U1.29 50.74,40.238 50.832,40.329 v2(50.899,40.329)
  Top Layer w0.4: v2(54.346,40.19) 54.367,40.211 54.517,40.211 Y1.3@55.371,41.065 ; C1.2 54.523,43.049 55.046,42.525 55.046,41.39 Y1.3@55.371,41.065 ; Y1.3@55.371,41.065 Y1.3 Y1.3@55.371,41.065
  Bottom Layer w0.4: v2(50.899,40.329) 51.831,40.329 51.953,40.207 54.329,40.207 v2(54.346,40.19)
XTAL_PM: C2.2 U1.30 Y1.1 | length 7.4
  Top Layer w0.254: U1.30 50.478,40.738 50.6,40.86 51.22,40.86 52.025,40.054 52.025,39.736 52.446,39.315 Y1.1
  Top Layer w0.4: Y1.1 53.196,37.659 53.573,37.282 C2.2
pads on no net: AE1.2 IC2. IC2.A8 IC2.B8 IC2.S1 IC2.S2 IC2.S3 IC2.S4 IC4.4 SW1.2 SW1.4 U1.4 U1.5 U1.12 U1.13 U1.14 U1.19

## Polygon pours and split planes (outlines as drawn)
GND on Bottom Layer "Bottom Layer-GND" (solid, remove dead copper, pour order 8): 66.504,-15.865 ccw(c66.504,-9.865) 72.504,-9.865 72.504,51.232 22.504,51.232 22.504,-9.865 ccw(c28.504,-9.865) 28.504,-15.865
GND on Top Layer "Top Layer-GND" (solid, remove dead copper, pour order 7): 66.504,-15.865 ccw(c66.504,-9.865) 72.504,-9.865 72.504,58.135 ccw(c66.508,58.135) 72.456,58.893 cw(c66.489,58.324) 72.483,58.324 72.483,51.232 22.504,51.232 22.504,-9.865 ccw(c28.504,-9.865) 28.504,-15.865
+3V3 on Int2 (PWR) (split plane): 66.836,63.617 67.166,63.587 67.494,63.537 67.819,63.467 68.138,63.378 68.452,63.27 68.758,63.143 69.057,62.998 69.346,62.835 69.624,62.655 69.891,62.458 70.146,62.246 70.388,62.018 70.615,61.777 70.828,61.522 71.024,61.255 71.204,60.976 71.367,60.687 71.513,60.389 71.639,60.082 71.748,59.769 71.837,59.449 71.906,59.125 71.956,58.797 71.986,58.467 71.996,58.154 71.994,58.135 71.994,-9.865 71.996,-9.884 71.986,-10.197 71.956,-10.527 71.906,-10.855 71.837,-11.179 71.748,-11.499 71.639,-11.812 71.513,-12.119 71.367,-12.417 71.204,-12.706 71.024,-12.985 70.828,-13.252 70.615,-13.507 70.388,-13.748 70.146,-13.976 69.891,-14.188 69.624,-14.385 69.346,-14.565 69.057,-14.728 68.758,-14.873 68.452,-15 68.138,-15.108 67.819,-15.197 67.494,-15.267 67.166,-15.317 66.836,-15.347 66.523,-15.356 66.504,-15.355 28.504,-15.355 28.486,-15.356 28.173,-15.347 27.842,-15.317 27.514,-15.267 27.19,-15.197 26.871,-15.108 26.557,-15 26.25,-14.873 25.952,-14.728 25.663,-14.565 25.385,-14.385 25.117,-14.188 24.863,-13.976 24.621,-13.748 24.394,-13.507 24.181,-13.252 23.985,-12.985 23.804,-12.706 23.642,-12.417 23.496,-12.119 23.369,-11.812 23.261,-11.499 23.172,-11.179 23.102,-10.855 23.052,-10.527 23.022,-10.197 23.013,-9.884 23.015,-9.865 23.015,58.135 23.013,58.154 23.022,58.467 23.052,58.797 23.102,59.125 23.172,59.449 23.261,59.769 23.369,60.082 23.496,60.389 23.642,60.687 23.804,60.976 23.985,61.255 24.181,61.522 24.394,61.777 24.621,62.018 24.863,62.246 25.117,62.458 25.385,62.655 25.663,62.835 25.952,62.998 26.25,63.143 26.557,63.27 26.871,63.378 27.19,63.467 27.514,63.537 27.842,63.587 28.173,63.617 28.486,63.626 28.504,63.625 66.504,63.625 66.523,63.626
GND on Int1 (GND) (split plane): 66.836,63.617 67.166,63.587 67.494,63.537 67.819,63.467 68.138,63.378 68.452,63.27 68.758,63.143 69.057,62.998 69.346,62.835 69.624,62.655 69.891,62.458 70.146,62.246 70.388,62.018 70.615,61.777 70.828,61.522 71.024,61.255 71.204,60.976 71.367,60.687 71.513,60.389 71.639,60.082 71.748,59.769 71.837,59.449 71.906,59.125 71.956,58.797 71.986,58.467 71.996,58.154 71.994,58.135 71.994,-9.865 71.996,-9.884 71.986,-10.197 71.956,-10.527 71.906,-10.855 71.837,-11.179 71.748,-11.499 71.639,-11.812 71.513,-12.119 71.367,-12.417 71.204,-12.706 71.024,-12.985 70.828,-13.252 70.615,-13.507 70.388,-13.748 70.146,-13.976 69.891,-14.188 69.624,-14.385 69.346,-14.565 69.057,-14.728 68.758,-14.873 68.452,-15 68.138,-15.108 67.819,-15.197 67.494,-15.267 67.166,-15.317 66.836,-15.347 66.523,-15.356 66.504,-15.355 28.504,-15.355 28.486,-15.356 28.173,-15.347 27.842,-15.317 27.514,-15.267 27.19,-15.197 26.871,-15.108 26.557,-15 26.25,-14.873 25.952,-14.728 25.663,-14.565 25.385,-14.385 25.117,-14.188 24.863,-13.976 24.621,-13.748 24.394,-13.507 24.181,-13.252 23.985,-12.985 23.804,-12.706 23.642,-12.417 23.496,-12.119 23.369,-11.812 23.261,-11.499 23.172,-11.179 23.102,-10.855 23.052,-10.527 23.022,-10.197 23.013,-9.884 23.015,-9.865 23.015,58.135 23.013,58.154 23.022,58.467 23.052,58.797 23.102,59.125 23.172,59.449 23.261,59.769 23.369,60.082 23.496,60.389 23.642,60.687 23.804,60.976 23.985,61.255 24.181,61.522 24.394,61.777 24.621,62.018 24.863,62.246 25.117,62.458 25.385,62.655 25.663,62.835 25.952,62.998 26.25,63.143 26.557,63.27 26.871,63.378 27.19,63.467 27.514,63.537 27.842,63.587 28.173,63.617 28.486,63.626 28.504,63.625 66.504,63.625 66.523,63.626

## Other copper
Top Layer:
  pour cut-out: 49.229,53.612 49.311,53.557 49.366,53.475 49.385,53.378 49.385,52.178 49.367,52.083 49.367,49.086 49.473,49.086 49.57,49.067 49.653,49.012 49.708,48.93 49.727,48.833 49.727,47.627 49.708,47.529 49.653,47.447 49.57,47.392 49.473,47.373 48.415,47.373 48.318,47.392 48.236,47.447 48.181,47.529 48.161,47.627 48.161,48.101 47.55,48.101 47.541,48.056 47.486,47.974 47.404,47.919 47.307,47.9 46.387,47.9 46.29,47.919 46.207,47.974 46.152,48.056 46.133,48.153 46.133,48.893 46.152,48.991 46.207,49.073 46.29,49.128 46.387,49.147 47.307,49.147 47.404,49.128 47.486,49.073 47.541,48.991 47.55,48.946 48.191,48.946 48.236,49.012 48.318,49.067 48.415,49.086 48.522,49.086 48.522,51.924 48.332,51.924 48.235,51.943 48.152,51.998 48.097,52.081 48.078,52.178 48.078,53.378 48.097,53.475 48.152,53.557 48.235,53.612 48.332,53.632 49.132,53.632

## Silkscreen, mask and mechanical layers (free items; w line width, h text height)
Top Overlay:
  text "2.4GHz" at 46.775,62.148 h1.52
  text "PWR" at 24.045,52.002 h1.52
  text "RESET" at 66.011,49.035 h1.52
  text "RX     TX" at 33.507,44.8 h1.52 r270
  text "+3V3 GND" at 33.53,39.368 h1.52 r270
  text "USB" at 71.154,38.23 h1.52 r90
  text "CTRL2" at 37.294,27.493 h1.52 r270
  text "PWR" at 62.396,22.824 h1.52 r90
  text "GND" at 62.374,18.686 h1.52 r90
  text "CTRL1" at 37.294,18.521 h1.52 r270
  text "A2   3V3" at 33.013,9.896 h1.52 r270
  text "A1   3V3" at 60.713,5.54 h1.52 r90
  text "GND  GND" at 32.988,1.579 h1.52 r270
  text "VBUS  3V3" at 60.713,-4.625 h1.52 r90
  text "RGB" at 45.157,-11.259 h1.52
Bottom Overlay:
  drawing of 81 lines, arcs and shapes, not listed
  text "Xylem V1.0" at 51.515,60.743 h1.52
  text "06.2024" at 49.032,58.408 h1.52
  text "by Oreoluwa" at 50.728,-7.075 h1.52
Board:
  the board outline again, w0.254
